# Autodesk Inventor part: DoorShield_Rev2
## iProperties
Created: 2009-01
Part Number: DoorShield_Rev2
Document SubType Name: Modeling
Designer: claivier
Material: Acier
Norme de conversion: STEP AP214IS
Nom du fichier: DoorShield_Rev2.STEP
Préprocesseur: SolidWorks 2008
Postprocesseur: Build: 344a, Release: 11 SP2 - Date: Fri 08/18/2006
Unités envoyées: INCHES
Incertitude: 1e-05
Author: claivier
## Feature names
1. Base1
